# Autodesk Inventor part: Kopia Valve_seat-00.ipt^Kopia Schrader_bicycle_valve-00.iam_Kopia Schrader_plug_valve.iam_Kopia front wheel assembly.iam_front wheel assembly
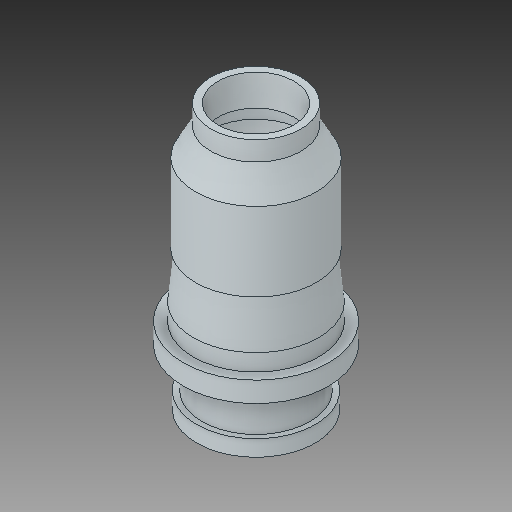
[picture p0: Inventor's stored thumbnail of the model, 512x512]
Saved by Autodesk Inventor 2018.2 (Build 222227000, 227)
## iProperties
Created: 2017-09
Part Number: Kopia Valve_seat-00.ipt^Kopia Schrader_bicycle_valve-00.iam_Kopia Schrader_plug_valve.iam_Kopia front wheel assembly.iam_front wheel assembly
Material: Ogólny
Document SubType Name: Modeling
Designer: Tomasz
Density: 1 g/cm^3
Appearance: Domyślna
Author: Tomasz
Sending System: SolidWorks 2017
Last Author: Tomasz
Last Saved: 2017-09-11
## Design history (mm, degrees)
feature "Valve_seat-00.ipt"
node "Bryła1"
